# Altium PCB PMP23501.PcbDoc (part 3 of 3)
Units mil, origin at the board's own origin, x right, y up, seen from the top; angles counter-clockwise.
Board outline 4950 x 3450 mil, 4 copper layers (Top Layer, Layer 1, Layer 2, Bottom Layer), stack 70.356 mil thick; 186 components, 84 nets, 554 pads, 643 vias.
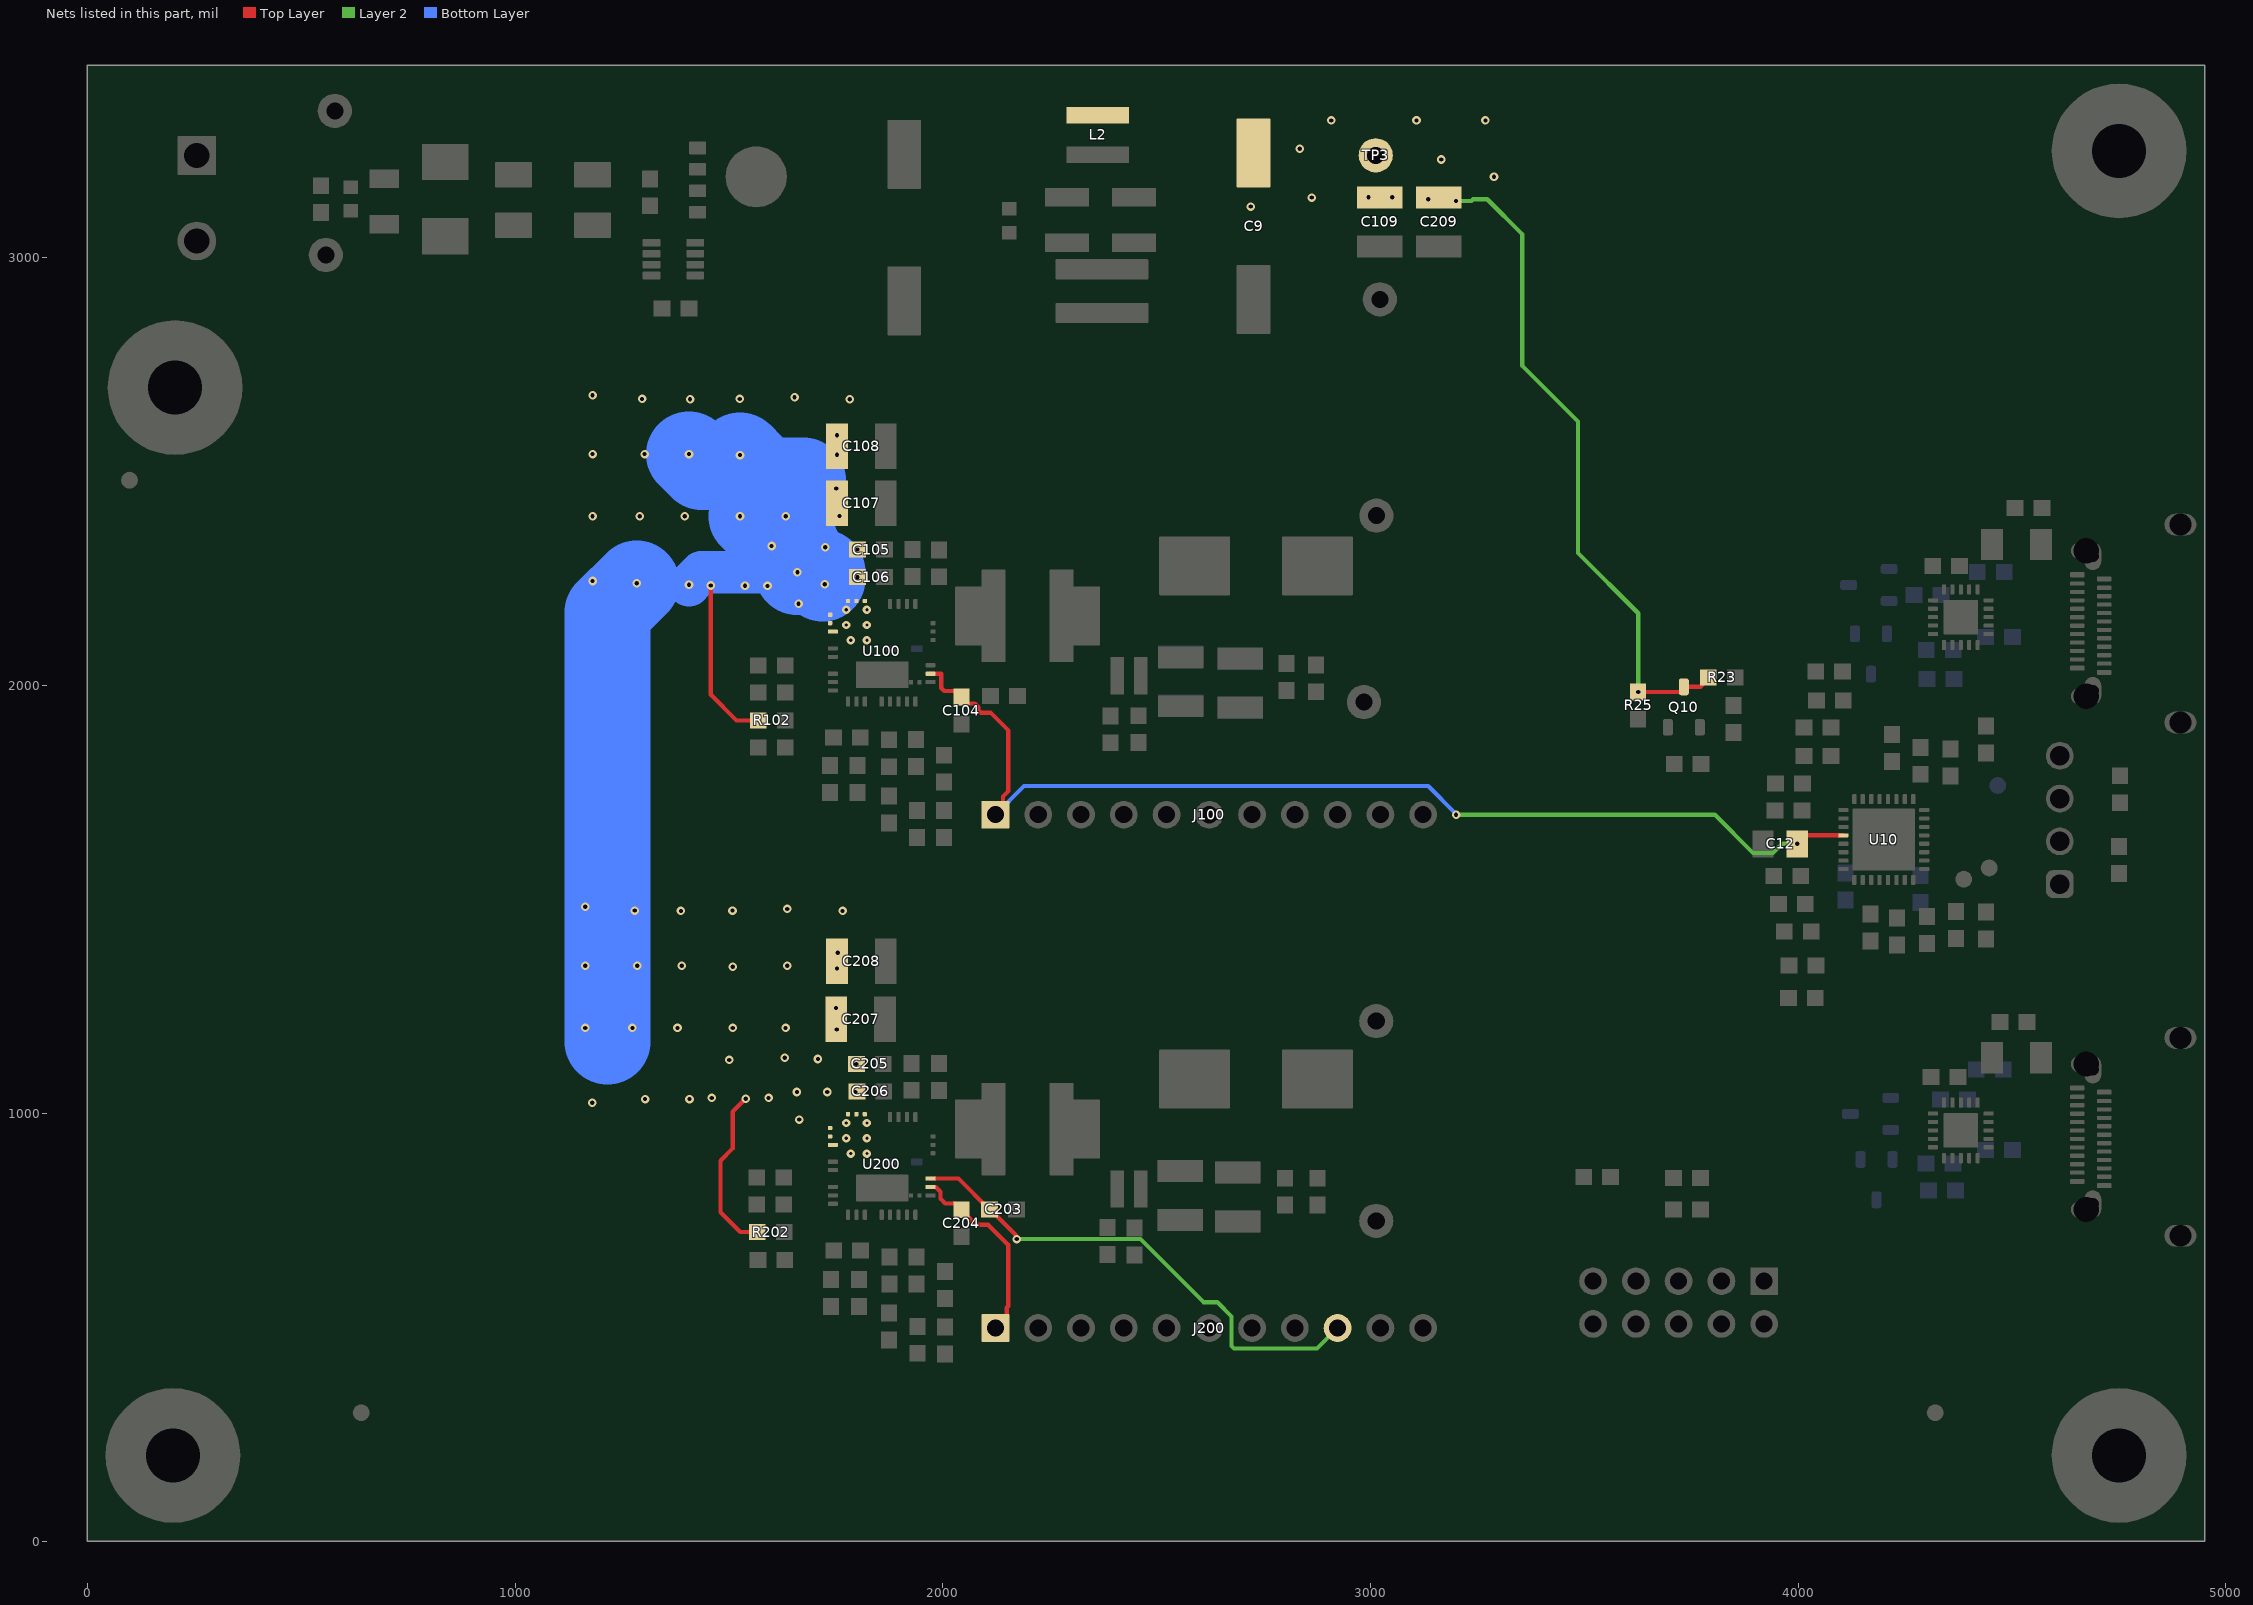
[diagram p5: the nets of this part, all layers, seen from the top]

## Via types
v1: diameter 20, hole 10, Top Layer to Bottom Layer, tented both sides, 592 vias
v2: diameter 19.68, hole 7.87, Top Layer to Bottom Layer, tented both sides, 46 vias
v3: diameter 16, hole 8, Top Layer to Bottom Layer, tented both sides, 4 vias
v4: diameter 20/20/20/20 (per signal layer), hole 10, Top Layer to Bottom Layer, tented bottom, 1 vias

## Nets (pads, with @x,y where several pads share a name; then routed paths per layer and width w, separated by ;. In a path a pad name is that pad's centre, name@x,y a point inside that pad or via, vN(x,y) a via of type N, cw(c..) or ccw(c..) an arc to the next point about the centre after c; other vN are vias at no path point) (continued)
VCC_B: C203.1 J200.9 U200.19 | length 1183.5
  Top Layer w10: U200.19@1971.17,847.47 2036.37,847.47 2108.29,775.56 C203.1@2109.27,775.56 2110.25,775.56 2171.09,714.73 2171.09,707.91 v1(2173,706) v1@2173,708.71
  Layer 2 w10: v1(2173,706) 2461.94,706 2609.44,558.5 2641.5,558.5 2675,525 2675,455.86 2680.86,450 2875,450 J200.9@2923,498
VDDA_A: C12.1 C104.2 J100.1 U10.4 U100.18 | length 2568.5
  Top Layer w10: U100.18@1970.75,2027.56 1996.23,2027.56 1996.23,1994.51 2003.27,1987.47 2029.8,1987.47 2043.5,1973.77 C104.2@2043.5,1972.95 C104.2@2051.04,1965.41 ; C104.2@2043.5,1958.11 2074.48,1958.11 2083.02,1949.57 2083.02,1942.62 2088.88,1936.76 2111.6,1936.76 2153.21,1895.15 2153.21,1753.35 2140.77,1740.9 2140.77,1715.96 J100.1@2122.99,1698.19 ; v1(3997.48,1630.16) 4017.17,1649.84 U10.4@4105.51,1649.84
  Layer 2 w10: v1(3200,1698) 3805,1698.19 3894.53,1608.66 3940.93,1608.66 3962.43,1630.16 v1(3997.48,1630.16)
  Bottom Layer w10: J100.1@2122.99,1698.19 2189.8,1765 3135,1765 3200,1700 v1(3200,1698)
VDDA_B: C204.2 J200.1 U200.18 | length 455.1
  Top Layer w10: U200.18@1971.17,827.79 1971.25,827.71 1983.41,827.71 1994.48,816.63 1994.48,800.52 2005.74,789.26 2029.8,789.26 2043.5,775.56 C204.2@2043.5,774.57 2043.5,773.59 2077.94,739.15 2106.29,739.15 2152.68,692.76 2152.68,548.86 2149.3,545.48 2149.3,524.3 J200.1@2123,498
Vin_48: C9.1 C105.1 C106.1 C107.1 C108.1 C109.1 C205.1 C206.1 C207.1 C208.1 C209.1 L2.2 Q10.3 R23.2 R25.1 R102.2 R202.2 TP3.1 U100.1 U100.2 U100.3 U100.27 U100.28 U100.29 U200.1 U200.2 U200.3 U200.27 U200.28 U200.29 | length 4583.7
  Top Layer w10: v1(1406.5,2235.51) v1@1408.31,2233.69 ; v1(1457.18,2234.06) 1457.18,1978.91 1517.44,1918.65 R102.2@1568.57,1918.65 ; v1(1538.99,1034) 1508.53,1003.54 1508.53,917.71 1479.98,889.17 1479.98,768.78 1526.36,722.4 R202.2@1566.25,722.4 R202.2@1561.36,727.3 ; v1(3625.85,1985.02) 3725.66,1985.02 3732.41,1991.77 Q10.3@3732.41,1996.98 3771.36,1996.98 3793.61,2019.24 R23.2@3797.55,2019.24
  Layer 2 w10: v1(3200,3133.17) 3235.82,3133.17 3239.77,3137.12 3272.88,3137.12 3355,3055 3355,2747.5 3485,2617.5 3485,2310 3625.85,2169.15 v1(3625.85,1985.02)
  Bottom Layer w100: v1(1406.5,2235.51) 1435.99,2265 v1(1660.05,2265)
  Bottom Layer w200: 1216.01,1167.65 1216.01,2171.39 v1(1284.13,2239.51) ; v1(1406.5,2541.24) 1436.86,2510.88 1521.43,2510.88 1551.79,2480.51 1674.17,2480.51 ; v1(1525.72,2539.01) 1551.79,2512.94 1551.79,2454.44 1601.29,2404.95 1601.29,2380.73 1660.05,2321.96 v1(1660.05,2265) ; 1660.05,2287.69 v1(1660.05,2265) ; 1660.05,2326.32 v1(1660.05,2265) ; 1719.31,2249.42 1719.31,2265 v1(1660.05,2265) ; 1551.79,2395.94 1579.6,2368.13 1551.79,2395.94
  other v1: 1664.11,985.27 1180,1025 1303.82,1033.2 1407.69,1033.2 1460,1035.94 1592.66,1035.94 1658.95,1049.82 1729.84,1049.82 1795.08,1049.82 1797.86,1115.52 1500.72,1124.71 1708,1126.99 1630.13,1130 1751.68,1195.94 1164.11,1199.71 1274.28,1199.71 1379.66,1199.71 1508.72,1199.71 1632.35,1199.71 1750.02,1246.36 1752.44,1338.5 1508.72,1342.77 1164.11,1345 1285.67,1345 1389.5,1345 1636.3,1345 1754.13,1375.5 1387.72,1473.08 1765.61,1473.08 1279.81,1473.96 1508.27,1473.96 1636.3,1477.8 1164.11,1482.66 1662.65,2191.17 1590,2233.02 1537.39,2233.69 1724.14,2236.97 1181.1,2244.6 1800.6,2253.32 1800.6,2318.1 1725,2323.23 1599.65,2326.32 1181.1,2395.94 1291.27,2395.94 1396.66,2395.94 1525.72,2395.94 1632.55,2395.94 1758.36,2396.32 1750.66,2461 1752.44,2539.69 1181.1,2541.24 1302.66,2541.24 1752.44,2585 1409,2669.32 1782.6,2669.32 1296.8,2670.2 1525.26,2670.2 1653.3,2674.04 1181.1,2678.9 2720,3120 3135,3137.12 2862.64,3141.07 2995,3141.73 3050.56,3141.73 3288.65,3190 3165,3230 2834.2,3255 2908.04,3321.35 3107.46,3321.35 3268.54,3321.35
  other v2: 1784.8,905.9 1822.55,905.9 1774.32,941.65 1822.55,941.65 1774.32,977.39 1822.55,977.39 1784.8,2105.9 1822.55,2105.9 1774.32,2141.65 1822.55,2141.65 1774.32,2177.39 1822.55,2177.39
pads on no net: FID1.1 FID2.1 FID3.1 H1.0 H2.1 H3.0 H4.1 H5.0 H6.1 H7.0 H8.1 J30.1 J30.2 J30.3 J30.4 J30.7 J30.8 J130.A2 J130.A3 J130.A8 J130.A10 J130.A11 J130.B2 J130.B3 J130.B8 J130.B10 J130.B11 J230.A2 J230.A3 J230.A8 J230.A10 J230.A11 J230.B2 J230.B3 J230.B8 J230.B10 J230.B11 LBL1.0 U1.3 U1.7 U1.8 U100.10 U140.9 U140.16 U140.17 U140.19 U140.20 U200.10 U240.9 U240.16 U240.17 U240.19 U240.20

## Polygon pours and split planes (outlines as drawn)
GND on Top Layer "TOP_LAYER_GND_P000" (solid, remove dead copper, pour order 0): 4105.5,2281.22 4105.5,2092.45 4133.7,2092.45 4522.18,2092.45 4522.18,2193.48 4409.77,2302.12 4391.21,2302.12 4126.4,2302.12
GND on Top Layer "TOP_LAYER_GND_P035" (solid, remove dead copper, pour order 35): 33.55,2863.05 1212.99,2863.05 1212.99,3442.34 4933.55,3442.34 4933.55,47.34 33.55,47.34
GND on Top Layer "TOP_LAYER_GND_P034" (solid, remove dead copper, pour order 34): 1872.2,2181.88 1937.29,2181.88 1937.29,2196.36 1929.4,2265 1891.31,2265 1891.31,2217.38 1872.2,2198.28
AGND_B on Top Layer "TOP_LAYER_AGND_B_P032" (solid, remove dead copper, pour order 32): 1959.77,816.63 1959.77,661.25 1787.04,661.25 1787.04,667.7 1784.8,669.94 1539,669.94 1539,587.71 1744.63,382.08 2156.36,382.08 2156.36,742.74 2063.4,742.74 1989.5,816.63
AGND_A on Top Layer "TOP_LAYER_AGND_A_P030" (solid, remove dead copper, pour order 30): 1960.51,2013.07 1959.21,2011.77 1959.21,1866.64 1786.48,1866.64 1786.48,1873.08 1784.24,1875.33 1550.04,1875.33 1550.04,1781.5 1741.54,1590 2155.8,1590 2155.8,1948.12 2062.84,1948.12 1997.89,2013.07
VBUS_B on Top Layer "TOP_LAYER_VBUS_B_P028" (solid, remove dead copper, pour order 28): 2710,1335 3457.28,1335 3457.28,1056.63 3457.28,818.19 2710,818.19
VBUS_B on Top Layer "TOP_LAYER_VBUS_B_P025" (solid, remove dead copper, pour order 25): 2440,760 2474.87,760 2485.7,770.83 2485.7,811.54 2754.19,811.54 2764.58,821.93 2984.2,821.93 2984.2,1134.11 3068.59,1218.5 3068.59,1224.69 3050.56,1224.69 3013.35,1261.91 2947.39,1195.94 2756.5,1195.94 2756.5,964.46 2440,964.46 2440,896.14
NetL200_2 on Top Layer "TOP_LAYER_NETL200_2_P024" (solid, remove dead copper, pour order 24): 2250,1065 2342.21,1065 2372.57,1034.64 2372.57,929.13 2375.07,929.13 2427.47,876.73 2427.47,799.28 2398.61,799.28 2250,799.28
VBUS_A on Top Layer "TOP_LAYER_VBUS_A_P023" (solid, remove dead copper, pour order 23): 2710,2465.59 4671.95,2465.59 4671.95,2018.19 2710,2018.19
GND on Top Layer "TOP_LAYER_GND_P022" (solid, remove dead copper, pour order 22): 1832.68,2805 1848.9,2821.22 1848.9,3094.57 3230,3094.57 3230,2950.97 3074.15,2795.13 2762.97,2795.13 2655,2903.09 2196.24,2903.09 2130,2836.85 2130,2800 1839.15,2800 1834.15,2805
Vin_48 on Top Layer "TOP_LAYER_VIN_48_P021" (solid, remove dead copper, pour order 21): 2290,3360 2290.07,3359.93 2290.07,3281.48 2568.52,3281.48 2598.55,3251.45 2598.55,3089.57 3307.79,3089.57 3328.74,3110.52 3328.74,3360
V_Batt_Protected on Top Layer "TOP_LAYER_V_BATT_PROTECTED_P020" (solid, remove dead copper, pour order 20): 1484.3,3336.61 2035.53,3336.61 2117.14,3255 2520,3255 2520,3094.57 2525,3089.57 1486.94,3089.57 1484.3,3092.21 1484.3,3334.06
NetC3_1 on Top Layer "TOP_LAYER_NETC3_1_P017" (solid, remove dead copper, pour order 17): 1216.01,3224.24 1292.02,3224.24 1330.01,3262.23 1450,3262.23 1450,3142.23 1455,3137.23 1450.08,3132.31 1387.69,3132.31 1370,3150 1369.42,3149.42 1216.01,3149.42
EMIGND on Top Layer "TOP_LAYER_EMIGND_P016" (solid, remove dead copper, pour order 16): 202.33,3134.43 200.88,3132.98 200.88,2984.41 958.5,2984.41 958.5,3141.37 192.15,3141.37
NetC0_1 on Top Layer "TOP_LAYER_NETC0_1_P013" (solid, remove dead copper, pour order 13): 202.33,3402.33 202.33,3134.43 961.07,3134.43 961.07,3290 739.41,3290 653.98,3375.43 653.98,3405.68 205.68,3405.68
VBUS_A on Top Layer "TOP_LAYER_VBUS_A_P012" (solid, remove dead copper, pour order 12): 2440,1960 2474.87,1960 2485.7,1970.83 2485.7,2011.54 2754.19,2011.54 2764.58,2021.93 2984.2,2021.93 2984.2,2334.11 3068.59,2418.5 3068.59,2424.69 3050.56,2424.69 3013.35,2461.91 2947.39,2395.94 2756.5,2395.94 2756.5,2164.46 2440,2164.46 2440,2096.14
NetL100_2 on Top Layer "TOP_LAYER_NETL100_2_P010" (solid, remove dead copper, pour order 10): 2250,2265 2342.21,2265 2372.57,2234.64 2372.57,2129.13 2375.07,2129.13 2427.47,2076.73 2427.47,1999.28 2398.61,1999.28 2250,1999.28
Vin_48 on Top Layer "TOP_LAYER_VIN_48_P009" (solid, remove dead copper, pour order 9): 1125,2712.8 1839.09,2712.8 1839.09,2114.28 1778.43,2114.28 1777.1,2112.95 1770.72,2119.32 1724.14,2119.32 1694.73,2166.38 1694.73,2169.45 1125,2169.45
Vin_48 on Top Layer "TOP_LAYER_VIN_48_P008" (solid, remove dead copper, pour order 8): 1125,1513 1839.09,1513 1839.09,914.47 1778.43,914.47 1777.1,913.14 1770.72,919.52 1724.14,919.52 1694.73,966.57 1694.73,969.64 1125,969.64
NetC212_1 on Top Layer "TOP_LAYER_NETC212_1_P007" (solid, remove dead copper, pour order 7): 2151.27,1075.4 2151.27,857.74 2147.72,854.18 2085.78,854.18 2085.78,860.83 2071.14,875.47 1851.16,876.8 1851.16,961.7 1852.05,962.59 1959.21,962.59 1959.21,1075.4
NetC112_1 on Top Layer "TOP_LAYER_NETC112_1_P004" (solid, remove dead copper, pour order 4): 2155.51,2277.93 2155.51,2055.92 2153.77,2054.18 2085.78,2054.18 2085.78,2060.83 2064.93,2081.69 1835.15,2081.69 1835.15,2168.54 1935.4,2168.54 1935.4,2277.93 2087.91,2277.93
VBUS_B on Top Layer "TOP_LAYER_VBUS_B_P003" (solid, remove dead copper, pour order 3): 3411.1,1176.31 4400.12,1176.3 4400.12,1205.8 4456.84,1262.51 4500.4,1262.51 4500.4,1129.6 4618.07,1011.93 4691.96,1011.93 4691.96,833.29 4670.23,811.57 3931.18,811.57 3814.16,928.59 3411.1,928.59
GND on Top Layer "TOP_LAYER_GND_P002" (solid, remove dead copper, pour order 2): 4111.98,1087.08 4111.98,870.29 4113.36,871.68 4520.19,871.68 4520.19,991.05 4407.78,1099.69 4389.22,1099.69 4124.4,1099.69 4109.71,1085
GND on Layer 1 "LAYER_1_GND_P005" (solid, remove dead copper, pour order 5): 6,3442 10,3438 10,16 4936,16 4940,12 4940,3438 6,3438 2,3434
Vin_48 on Bottom Layer "BOTTOM_LAYER_VIN_48_P027" (solid, remove dead copper, pour order 27): 2845,3315 2889.93,3359.93 3325,3359.93 3325,3069.89 3314.32,3059.21 3062.23,3059.21 2184.9,2181.88 2176.7,2190.08 1751.67,2190.08 1751.67,2593.27 1813.41,2655 2186.24,2655 2851.94,3320.7
GND on Bottom Layer "BOTTOM_LAYER_GND_P033" (solid, remove dead copper, pour order 33): 24.43,2834.35 1210.59,2834.35 1210.59,3421.55 4924.43,3421.55 4924.43,26.55 24.43,26.55
Vin_48 on Bottom Layer "BOTTOM_LAYER_VIN_48_P015" (solid, remove dead copper, pour order 15): 1122.46,1513 1122.46,969.64 1659.7,969.64 1757.81,871.54 1839.09,871.54 1839.09,1513
Vin_48 on Bottom Layer "BOTTOM_LAYER_VIN_48_P014" (solid, remove dead copper, pour order 14): 1125,2712.8 1125,2141.42 1695.47,2141.42 1741.48,2095.41 1858.04,2095.41 1858.04,2712.8
GND on Layer 2 "LAYER_2_GND_P029" (solid, remove dead copper, pour order 29): 21.51,2840 1210,2840 1210,3420.06 4921.51,3420.06 4921.51,25.06 21.51,25.06

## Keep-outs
Keep-Out Layer:
  lines w5: -2.5,0 ccw(c0,0) 0,-2.5 ; -2.5,0 ccw(c0,0) 0,-2.5 ; -2.5,0 -2.5,3450 ; -2.5,3450 cw(c0,3450) 0,3452.5 ; -2.5,3450 cw(c0,3450) 0,3452.5 ; 0,-2.5 4950,-2.5 ; 0,3452.5 4950,3452.5 ; 4741.4,755.06 ccw(c4743.9,755.06) 4741.59,754.1 ; 4741.4,755.06 ccw(c4743.9,755.06) 4741.58,754.11 ; 4741.4,755.06 4741.4,758.95 ; 4741.4,758.95 cw(c4743.9,758.98) 4741.4,758.98 ; 4741.4,758.95 cw(c4743.9,758.98) 4741.4,758.98 ; 4741.4,758.95 4741.4,758.98 ; 4741.4,758.98 4741.4,1131.02 4741.4,1134.94 ; 4741.4,1134.94 cw(c4743.9,1134.94) 4741.58,1135.89 ; 4741.4,1134.94 cw(c4743.9,1134.94) 4741.59,1135.9 ; 4741.4,1955.06 ccw(c4743.9,1955.06) 4741.59,1954.1 ; 4741.4,1955.06 ccw(c4743.9,1955.06) 4741.58,1954.11 ; 4741.4,1955.06 4741.4,1958.95 ; 4741.4,1958.95 cw(c4743.9,1958.98) 4741.4,1958.98 ; 4741.4,1958.95 cw(c4743.9,1958.98) 4741.4,1958.98 ; 4741.4,1958.95 4741.4,1958.98 ; 4741.4,1958.98 4741.4,2331.02 4741.4,2334.94 ; 4741.4,2334.94 cw(c4743.9,2334.94) 4741.58,2335.89 ; 4741.4,2334.94 cw(c4743.9,2334.94) 4741.59,2335.9 ; 4741.58,754.11 ccw(c4743.9,755.06) 4741.59,754.1 ; 4741.58,754.11 4741.59,754.1 ; 4741.59,754.1 4741.59,754.1 ; 4741.59,754.1 4744.58,746.88 ; 4741.59,1135.9 ccw(c4743.9,1134.94) 4741.58,1135.89 ; 4741.59,1135.9 4744.58,1143.12 ; 4741.59,1135.9 4741.59,1135.9 ; 4741.58,1135.89 4741.59,1135.9 ; 4741.58,1954.11 ccw(c4743.9,1955.06) 4741.59,1954.1 ; 4741.58,1954.11 4741.59,1954.1 ; 4741.59,1954.1 4741.59,1954.1 ; 4741.59,1954.1 4744.58,1946.88 ; 4741.59,2335.9 ccw(c4743.9,2334.94) 4741.58,2335.89 ; 4741.59,2335.9 4744.58,2343.12 ; 4741.59,2335.9 4741.59,2335.9 ; 4741.58,2335.89 4741.59,2335.9 ; 4744.58,746.87 ccw(c4746.89,747.83) 4745.13,746.06 ; 4744.59,746.86 ccw(c4746.89,747.83) 4745.13,746.06 ; 4744.59,746.86 cw(c4746.89,747.83) 4744.58,746.88 ; 4744.58,746.87 4744.58,746.88 ; 4744.58,746.87 4744.59,746.86 ; 4744.58,1143.12 cw(c4746.89,1142.17) 4744.59,1143.14 ; 4744.58,1143.12 4744.58,1143.13 ; 4744.58,1143.13 cw(c4746.89,1142.17) 4745.13,1143.94 ; 4744.59,1143.14 cw(c4746.89,1142.17) 4745.13,1143.94 ; 4744.58,1143.13 4744.59,1143.14 ; 4744.58,1946.87 ccw(c4746.89,1947.83) 4745.13,1946.06 ; 4744.59,1946.86 ccw(c4746.89,1947.83) 4745.13,1946.06 ; 4744.59,1946.86 cw(c4746.89,1947.83) 4744.58,1946.88 ; 4744.58,1946.87 4744.58,1946.88 ; 4744.58,1946.87 4744.59,1946.86 ; 4744.58,2343.12 cw(c4746.89,2342.17) 4744.59,2343.14 ; 4744.58,2343.12 4744.58,2343.13 ; 4744.58,2343.13 cw(c4746.89,2342.17) 4745.13,2343.94 ; 4744.59,2343.14 cw(c4746.89,2342.17) 4745.13,2343.94 ; 4744.58,2343.13 4744.59,2343.14 ; 4745.13,746.06 4750.66,740.52 ; 4745.13,1143.94 4750.66,1149.48 ; 4745.13,1946.06 4750.66,1940.52 ; 4745.13,2343.94 4750.66,2349.48 ; 4746.4,758.98 ccw(c4743.9,758.98) 4746.4,759 ; 4746.4,758.98 ccw(c4743.9,758.98) 4746.4,759 ; 4746.4,759 4746.4,1131.02 4746.4,1134.44 4749.01,1140.76 4753.85,1145.59 4760.16,1148.21 4767,1148.21 4773.32,1145.59 4778.15,1140.76 4780.77,1134.44 4780.77,1131.02 ; 4746.4,758.98 4746.4,759 ; 4746.4,758.98 4746.4,755.56 4749.01,749.24 4753.85,744.41 4760.16,741.79 4767,741.79 4773.32,744.41 4778.15,749.24 4780.77,755.56 4780.77,758.98 ; 4746.4,1958.98 ccw(c4743.9,1958.98) 4746.4,1959 ; 4746.4,1958.98 ccw(c4743.9,1958.98) 4746.4,1959 ; 4746.4,1959 4746.4,2331.02 4746.4,2334.44 4749.01,2340.76 4753.85,2345.59 4760.16,2348.21 4767,2348.21 4773.32,2345.59 4778.15,2340.76 4780.77,2334.44 4780.77,2331.02 ; 4746.4,1958.98 4746.4,1959 ; 4746.4,1958.98 4746.4,1955.56 4749.01,1949.24 4753.85,1944.41 4760.16,1941.79 4767,1941.79 4773.32,1944.41 4778.15,1949.24 4780.77,1955.56 4780.77,1958.98 ; 4750.66,740.52 ccw(c4752.43,742.29) 4751.47,739.98 ; 4750.66,740.52 ccw(c4752.43,742.29) 4751.47,739.98 ; 4750.66,1149.48 cw(c4752.43,1147.71) 4751.47,1150.02 ; 4750.66,1149.48 cw(c4752.43,1147.71) 4751.47,1150.02 ; 4750.66,1940.52 ccw(c4752.43,1942.29) 4751.47,1939.98 ; 4750.66,1940.52 ccw(c4752.43,1942.29) 4751.47,1939.98 ; 4750.66,2349.48 cw(c4752.43,2347.71) 4751.47,2350.02 ; 4750.66,2349.48 cw(c4752.43,2347.71) 4751.47,2350.02 ; 4751.47,739.98 ccw(c4752.43,742.29) 4751.48,739.97 ; 4751.47,739.98 4751.48,739.97 ; 4751.47,739.98 4751.47,739.98 ; 4751.47,1150.02 cw(c4752.43,1147.71) 4751.48,1150.03 ; 4751.47,1150.02 4751.48,1150.03 ; 4751.47,1150.02 4751.47,1150.02 ; 4751.47,1939.98 ccw(c4752.43,1942.29) 4751.48,1939.97 ; 4751.47,1939.98 4751.48,1939.97 ; 4751.47,1939.98 4751.47,1939.98 ; 4751.47,2350.02 cw(c4752.43,2347.71) 4751.48,2350.03 ; 4751.47,2350.02 4751.48,2350.03 ; 4751.47,2350.02 4751.47,2350.02 ; 4751.48,739.97 4758.7,736.98 ; 4751.48,1150.03 4758.7,1153.02 ; 4751.48,1939.97 4758.7,1936.98 ; 4751.48,2350.03 4758.7,2353.02 ; 4758.72,736.98 ccw(c4759.67,739.29) 4759.67,736.79 ; 4758.7,736.98 ccw(c4759.67,739.29) 4758.72,736.98 ; 4758.71,736.98 ccw(c4759.67,739.29) 4759.67,736.79 ; 4758.71,736.98 4758.72,736.98 ; 4758.7,736.98 4758.71,736.98 ; 4758.71,1153.02 cw(c4759.67,1150.71) 4759.67,1153.21 ; 4758.72,1153.02 ccw(c4759.67,1150.71) 4758.7,1153.02 ; 4758.72,1153.02 cw(c4759.67,1150.71) 4759.67,1153.21 ; 4758.71,1153.02 4758.72,1153.02 ; 4758.7,1153.02 4758.71,1153.02 ; 4758.71,1936.98 ccw(c4759.67,1939.29) 4759.67,1936.79 ; 4758.72,1936.98 ccw(c4759.67,1939.29) 4759.67,1936.79 ; 4758.7,1936.98 ccw(c4759.67,1939.29) 4758.72,1936.98 ; 4758.71,1936.98 4758.72,1936.98 ; 4758.7,1936.98 4758.71,1936.98 ; 4758.71,2353.02 cw(c4759.67,2350.71) 4759.67,2353.21 ; 4758.72,2353.02 ccw(c4759.67,2350.71) 4758.7,2353.02 ; 4758.72,2353.02 cw(c4759.67,2350.71) 4759.67,2353.21 ; 4758.71,2353.02 4758.72,2353.02 ; 4758.7,2353.02 4758.71,2353.02 ; 4759.67,736.79 4767.5,736.79 ; 4759.67,1153.21 4767.5,1153.21 ; 4759.67,1936.79 4767.5,1936.79 ; 4759.67,2353.21 4767.5,2353.21 ; 4767.5,736.79 ccw(c4767.5,739.29) 4768.45,736.98 ; 4767.5,736.79 ccw(c4767.5,739.29) 4768.46,736.98 ; 4767.5,1153.21 cw(c4767.5,1150.71) 4768.45,1153.02 ; 4767.5,1153.21 cw(c4767.5,1150.71) 4768.46,1153.02 ; 4767.5,1936.79 ccw(c4767.5,1939.29) 4768.45,1936.98 ; 4767.5,1936.79 ccw(c4767.5,1939.29) 4768.46,1936.98 ; 4767.5,2353.21 cw(c4767.5,2350.71) 4768.45,2353.02 ; 4767.5,2353.21 cw(c4767.5,2350.71) 4768.46,2353.02 ; 4768.45,736.98 ccw(c4767.5,739.29) 4768.46,736.98 ; 4768.46,736.98 4775.68,739.97 ; 4768.46,736.98 4768.46,736.98 ; 4768.45,736.98 4768.46,736.98 ; 4768.46,1153.02 ccw(c4767.5,1150.71) 4768.45,1153.02 ; 4768.46,1153.02 4775.68,1150.03 ; 4768.46,1153.02 4768.46,1153.02 ; 4768.45,1153.02 4768.46,1153.02 ; 4768.45,1936.98 ccw(c4767.5,1939.29) 4768.46,1936.98 ; 4768.46,1936.98 4775.68,1939.97 ; 4768.46,1936.98 4768.46,1936.98 ; 4768.45,1936.98 4768.46,1936.98 ; 4768.46,2353.02 ccw(c4767.5,2350.71) 4768.45,2353.02 ; 4768.46,2353.02 4775.68,2350.03 ; 4768.46,2353.02 4768.46,2353.02 ; 4768.45,2353.02 4768.46,2353.02 ; 4775.68,739.97 ccw(c4774.73,742.29) 4775.7,739.98 ; 4775.68,739.97 4775.69,739.98 ; 4775.69,739.98 ccw(c4774.73,742.29) 4776.5,740.52 ; 4775.7,739.98 ccw(c4774.73,742.29) 4776.5,740.52 ; 4775.69,739.98 4775.7,739.98 ; 4775.69,1150.02 cw(c4774.73,1147.71) 4776.5,1149.48 ; 4775.7,1150.02 ccw(c4774.73,1147.71) 4775.68,1150.03 ; 4775.7,1150.02 cw(c4774.73,1147.71) 4776.5,1149.48 ; 4775.69,1150.02 4775.7,1150.02 ; 4775.69,1150.02 4775.68,1150.03 ; 4775.68,1939.97 ccw(c4774.73,1942.29) 4775.7,1939.98 ; 4775.68,1939.97 4775.69,1939.98 ; 4775.69,1939.98 ccw(c4774.73,1942.29) 4776.5,1940.52 ; 4775.7,1939.98 ccw(c4774.73,1942.29) 4776.5,1940.52 ; 4775.69,1939.98 4775.7,1939.98 ; 4775.69,2350.02 cw(c4774.73,2347.71) 4776.5,2349.48 ; 4775.7,2350.02 ccw(c4774.73,2347.71) 4775.68,2350.03 ; 4775.7,2350.02 cw(c4774.73,2347.71) 4776.5,2349.48 ; 4775.69,2350.02 4775.7,2350.02 ; 4775.69,2350.02 4775.68,2350.03 ; 4776.5,740.52 4782.04,746.06 ; 4776.5,1149.48 4782.04,1143.94 ; 4776.5,1940.52 4782.04,1946.06 ; 4776.5,2349.48 4782.04,2343.94 ; 4780.77,758.98 cw(c4783.27,758.98) 4783.27,761.48 ; 4780.77,758.98 cw(c4783.27,758.98) 4783.27,761.48 ; 4780.77,1131.02 ccw(c4783.27,1131.02) 4783.27,1128.52 ; 4780.77,1131.02 ccw(c4783.27,1131.02) 4783.27,1128.52 ; 4780.77,1958.98 cw(c4783.27,1958.98) 4783.27,1961.48 ; 4780.77,1958.98 cw(c4783.27,1958.98) 4783.27,1961.48 ; 4780.77,2331.02 ccw(c4783.27,2331.02) 4783.27,2328.52 ; 4780.77,2331.02 ccw(c4783.27,2331.02) 4783.27,2328.52 ; 4782.04,746.06 ccw(c4780.27,747.83) 4782.58,746.86 ; 4782.04,746.06 ccw(c4780.27,747.83) 4782.58,746.87 ; 4782.04,1143.94 cw(c4780.27,1142.17) 4782.58,1143.13 ; 4782.04,1143.94 cw(c4780.27,1142.17) 4782.58,1143.14 ; 4782.04,1946.06 ccw(c4780.27,1947.83) 4782.58,1946.86 ; 4782.04,1946.06 ccw(c4780.27,1947.83) 4782.58,1946.87 ; 4782.04,2343.94 cw(c4780.27,2342.17) 4782.58,2343.14 ; 4782.04,2343.94 cw(c4780.27,2342.17) 4782.58,2343.13 ; 4782.58,746.86 ccw(c4780.27,747.83) 4782.58,746.88 ; 4782.58,746.87 4782.59,746.88 ; 4782.58,746.86 4782.58,746.87 ; 4782.59,746.88 4785.57,754.09 ; 4782.58,1143.12 ccw(c4780.27,1142.17) 4782.58,1143.14 ; 4782.59,1143.12 4782.58,1143.13 ; 4782.59,1143.12 4785.57,1135.9 ; 4782.58,1143.14 4782.58,1143.13 ; 4782.58,1946.86 ccw(c4780.27,1947.83) 4782.58,1946.88 ; 4782.58,1946.87 4782.59,1946.88 ; 4782.58,1946.86 4782.58,1946.87 ; 4782.59,1946.88 4785.57,1954.09 ; 4782.58,2343.12 ccw(c4780.27,2342.17) 4782.58,2343.14 ; 4782.59,2343.12 4782.58,2343.13 ; 4782.59,2343.12 4785.57,2335.9 ; 4782.58,2343.14 4782.58,2343.13 ; 4783.27,761.48 4950,761.48 ; 4783.27,1128.52 4950,1128.52 ; 4783.27,1961.48 4950,1961.48 ; 4783.27,2328.52 4950,2328.52 ; 4785.57,754.1 ccw(c4783.27,755.06) 4785.58,754.11 ; 4785.57,754.09 4785.58,754.1 ; 4785.57,1135.9 cw(c4783.27,1134.94) 4785.58,1135.89 ; 4785.57,1135.9 4785.58,1135.9 ; 4785.57,1954.1 ccw(c4783.27,1955.06) 4785.58,1954.11 ; 4785.57,1954.09 4785.58,1954.1 ; 4785.57,2335.9 cw(c4783.27,2334.94) 4785.58,2335.89 ; 4785.57,2335.9 4785.58,2335.9 ; 4785.58,754.11 ccw(c4783.27,755.06) 4785.77,755.06 ; 4785.58,754.1 ccw(c4783.27,755.06) 4785.77,755.06 ; 4785.58,754.1 4785.58,754.11 ; 4785.58,1135.9 cw(c4783.27,1134.94) 4785.77,1134.94 ; 4785.58,1135.89 cw(c4783.27,1134.94) 4785.77,1134.94 ; 4785.58,1135.9 4785.58,1135.89 ; 4785.58,1954.1 ccw(c4783.27,1955.06) 4785.77,1955.06 ; 4785.58,1954.11 ccw(c4783.27,1955.06) 4785.77,1955.06 ; 4785.58,1954.1 4785.58,1954.11 ; 4785.58,2335.89 cw(c4783.27,2334.94) 4785.77,2334.94 ; 4785.58,2335.9 cw(c4783.27,2334.94) 4785.77,2334.94 ; 4785.58,2335.9 4785.58,2335.89 ; 4785.77,755.06 4785.77,756.48 4947.5,756.48 4947.5,2.5 2.5,2.5 2.5,3447.5 4947.5,3447.5 4947.5,2333.52 4785.77,2333.52 4785.77,2334.94 ; 4785.77,1134.94 4785.77,1133.52 4947.5,1133.52 4947.5,1956.48 4785.77,1956.48 4785.77,1955.06 ; 4950,-2.5 ccw(c4950,0) 4952.5,0 ; 4950,-2.5 ccw(c4950,0) 4952.5,0 ; 4950,761.48 cw(c4950,758.98) 4952.5,758.98 ; 4950,761.48 cw(c4950,758.98) 4952.5,758.98 ; 4950,1128.52 ccw(c4950,1131.02) 4952.5,1131.02 ; 4950,1128.52 ccw(c4950,1131.02) 4952.5,1131.02 ; 4950,1961.48 cw(c4950,1958.98) 4952.5,1958.98 ; 4950,1961.48 cw(c4950,1958.98) 4952.5,1958.98 ; 4950,2328.52 ccw(c4950,2331.02) 4952.5,2331.02 ; 4950,2328.52 ccw(c4950,2331.02) 4952.5,2331.02 ; 4950,3452.5 cw(c4950,3450) 4952.5,3450 ; 4950,3452.5 cw(c4950,3450) 4952.5,3450 ; 4952.5,0 4952.5,758.98 ; 4952.5,1131.02 4952.5,1958.98 ; 4952.5,2331.02 4952.5,3450
  text ".Layer_Name" at 577,-858.49 h60

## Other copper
Top Layer:
  text ".Layer_Name" at 577,-858.49 h60
Layer 1:
  pour cut-out: 10,3437.79 10,2840 1210,2840 1210,3434.79 13,3434.79
Bottom Layer:
  text ".Layer_Name" at 577,-858.49 h60

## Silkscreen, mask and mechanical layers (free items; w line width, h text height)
Top Overlay:
  text "Vin +" at 33.62,3390.55 h75
  text "Vin to DCDCs" at 3074.15,3257.22 h50
  text "GND" at 3088.73,2893.79 h50
  text "Vin -" at 63.28,2870 h75
  text "24Vin / 48Vin for SPR" at 446.29,2740.67 h60
  text "48Vin for EPR" at 463.98,2611.55 h30
  text "20Vout / 5A max for SPR" at 4295.91,2605.67 h60
  text "48Vout / 5A max for EPR" at 4301.22,2545.67 h60
  text "10A max" at 545.77,2486.32 h30
  text "CAUTION:" at 2018.3,2393.21 h60
  text "Hot Surface" at 2275.69,2393.21 h60
  text "VBUS_A" at 3000.05,2290.4 h50
  text "GND" at 3047.49,1976.44 h50
  text "debug" at 4480.52,1862.17 h30
  text "I2C to Host data" at 4364.4,1726.61 h30
  text "I2C to H. clock" at 4387.79,1648.47 h30
  text "DCDC_A" at 2715,1638.8 h30 r270
  text "PA_SYNC" at 2206.19,1636.12 h30 r270
  text "EN/UVLO_A" at 2415.79,1636.12 h30 r270
  text "COMP_A" at 2616.72,1634.16 h30 r270
  text "nINT-DCDCs" at 2792.13,1634.16 h30 r270
  text "IMON_A" at 3015.91,1631.65 h30 r270
  text "VCC_A" at 2915.22,1630.93 h30 r270
  text "VDDA_A" at 2083.26,1629.97 h30 r270
  text "GND" at 2307.34,1629.97 h30 r270
  text "GND" at 2521.91,1629.97 h30 r270
  text "GND" at 3121.91,1627.82 h30 r270
  text "'.PRJ_Number'.PCB_Rev" at 161.98,1605 h108.27
  text "GND" at 4688.54,1509.98 h30 r90
  text "DCDC_B" at 2895.05,1293.18 h50
  text "Hot Surface" at 2275,1216.18 h60
  text "CAUTION:" at 2014.99,1214.4 h60
  text "GND" at 3046.93,669.03 h50
  text "20Vout / 5A max for SPR" at 4291.05,640.71 h60
  text "48Vout / 5A max for EPR" at 4293.12,562.2 h60
  text "EN/UVLO_B" at 2410.67,433.31 h30 r270
  text "COMP_B" at 2630.32,433.31 h30 r270
  text "GND" at 2281.3,431.55 h30 r270
  text "GND" at 2513.92,431.55 h30 r270
  text "PB_SYNC" at 2206.19,431.12 h30 r270
  text "DCDC_B" at 2715.23,430.8 h30 r270
  text "VCC_B" at 2895.05,430.77 h30 r270
  text "IMON_B" at 3015.92,430.8 h30 r270
  text "VDDA_B" at 2083.44,427.77 h30 r270
  text "nINT-DCDCs" at 2810.24,422.3 h30 r270
  text "GND" at 3121.92,417.96 h30 r270
  text "I2C for DCDCs" at 3503.98,313.55 h60
  text ".Layer_Name" at 577,-858.49 h60
Bottom Overlay:
  text ".Layer_Name" at 577,-858.49 h60
Top Paste:
  text ".Layer_Name" at 577,-858.49 h60
Bottom Paste:
  text ".Layer_Name" at 577,-858.49 h60
Top Solder:
  text ".Layer_Name" at 577,-858.49 h60
  text ".Layer_Name" at 577,-858.49 h60
Bottom Solder:
  text ".Layer_Name" at 577,-858.49 h60
Drill Guide:
  text ".Layer_Name" at 577,-858.49 h60
M1 Board Outline:
  the board outline again, w10
  text ".Layer_Name" at 577,-858.49 h60
M2 Board Dimensions:
  rectangle: 0,-275 125,-150
  rectangle: 125,-400 500,-275
  lines w7: 0,-275 1000,-275 ; 125,-400 125,-150 ; 250,-400 250,-150 ; 500,-400 500,-150 ; 750,-400 750,-150 ; 0,-400 1000,-400 1000,-150 0,-150 0,-400
  text ".Layer_Name" at 577,-858.49 h60
M3 3D STEP Top:
  text ".Layer_Name" at 577,-858.49 h60
M4 3D STEP Bottom:
  text ".Layer_Name" at 577,-858.49 h60
M5 Assembly Top:
  lines w10: -292,-930.17 6308,-930.17 ; -292,-726.83 6310,-726.83 ; -292,-523.5 -292,-1133.5 3713,-1133.5 6310,-1133.5 6310,-523.5 -291.5,-523.5 -291.5,-1133.5 1284,-1133.5 ; 2173,-1133.5 2173,-523.5 ; 3440,-726.83 3440,-523.5 ; 4280,-726.83 4280,-523.5 ; 4902,-1140 4902,-937.17
  text "COMPONENTS MARKED 'DNP' SHOULD NOT BE POPULATED." at 1153.5,-318.5 h60
  text "ASSEMBLY VARIANT:" at 1153,-434 h60
  text ".VariantName" at 2189,-434 h60
  text "PCB VIEWED FROM TOP SIDE" at -228.5,-655.67 h60
  text "BOARD #:" at 2248,-655.67 h60
  text ".PRJ_Number" at 2793.5,-655.67 h60
  text "REV:" at 3638,-655.67 h60
  text ".PCB_Rev" at 3929.5,-655.67 h60
  text "SVN REV:" at 4476,-655.67 h60
  text ".VersionControl_RevNumber" at 4982,-655.67 h60
  text "TID #:" at 2248,-859 h60
  text ".TID" at 2793.5,-859 h60
  text "PLOT NAME =" at -228.5,-1064.34 h60
  text ".plot_File_Name" at 577,-1064.34 h60
  text "GENERATED    :" at 2250,-1064.34 h60
  text ".Print_Date" at 3119.5,-1064.34 h60
  text ".Print_Time" at 3848.5,-1064.34 h60
  text "TEXAS INSTRUMENTS" at 5113,-1064.34 h60
M6 Assembly Bottom:
  lines w10: -292.5,-727.33 6309.5,-727.33 ; -290.5,-930.67 6309.5,-930.67 ; 1115.5,-1140.5 1115.5,-937.67 ; 1737.5,-727.33 1737.5,-524 ; 2577.5,-727.33 2577.5,-524 ; 3844.5,-1134 3844.5,-524 ; 4733.5,-1134 6309,-1134 6309,-524 -292.5,-524 -292.5,-1134 2304.5,-1134 6309.5,-1134 6309.5,-524
  text "COMPONENTS MARKED 'DNP' SHOULD NOT BE POPULATED." at 6102,-318 h60
  text ".VariantName" at 5058,-434 h60
  text "ASSEMBLY VARIANT:" at 6097,-434 h60
  text ".VersionControl_RevNumber" at 1035.5,-656.17 h60
  text "SVN REV:" at 1541.5,-656.17 h60
  text ".PCB_Rev" at 2088,-656.17 h60
  text "REV:" at 2379.5,-656.17 h60
  text ".PRJ_Number" at 3224,-656.17 h60
  text "BOARD #:" at 3769.5,-656.17 h60
  text "PCB VIEWED FROM BOTTOM SIDE" at 6246,-656.17 h60
  text ".TID" at 3224,-859.5 h60
  text "TID #:" at 3769.5,-859.5 h60
  text "TEXAS INSTRUMENTS" at 904.5,-1064.84 h60
  text ".Print_Time" at 2169,-1064.84 h60
  text ".Print_Date" at 2898,-1064.84 h60
  text "GENERATED    :" at 3767.5,-1064.84 h60
  text ".plot_File_Name" at 5440.5,-1064.84 h60
  text "PLOT NAME =" at 6246,-1064.84 h60
M9 Title Sheet:
  drawing of 57 lines, arcs and shapes, not listed
  text "1" at 739.84,8036.5 h70
  text "2" at 3235.5,8036.5 h70
  text "3" at 5724.84,8036.5 h70
  text "4" at 8231.51,8036.5 h70
  text "5" at 10730.5,8036.5 h70
  text "6" at 13235.5,8036.5 h70
  text "A" at -416.5,6893.5 h70
  text "A" at 14383.5,6893.5 h70
  text "B" at -416.5,4513.5 h70
  text "B" at 14383.5,4513.5 h70
  text "C" at -416.5,2138.5 h70
  text "C" at 14383.5,2138.5 h70
  text "PROJECT TITLE:" at 11343.5,277.5 h45
  text ".PRJ_Title" at 11393.5,144.17 h70
  text "DESIGNED FOR:" at 11343.5,-23.5 h45
  text ".PRJ_Customer" at 11393.5,-163.5 h70
  text "D" at -416.5,-231.5 h70
  text "D" at 14383.5,-231.5 h70
  text "FILE NAME:" at 11343.5,-323.5 h45
  text ".PCB_File_Name_No_Path" at 11393.5,-443.5 h70
  text "Texas Instruments (TI) and/or its licensors do not warrant the accuracy or completeness of this specification" at 6374,-605.34 h45
  text "ENGINEER:" at 11343.5,-613.5 h45
  text "LAYOUT BY:" at 12848.5,-613.5 h45
  text "or any information contained therein. TI and/or its licensors do not warrant that this design will meet" at 6329.01,-718 h45
  text ".PRJ_Engineer" at 11393.5,-768.49 h70
  text ".PCB_Layout" at 12899,-768.49 h70
  text "the specifications, will be suitable for your application or fit for any particular purpose, or will operate in" at 6329.01,-830.67 h45
  text ".Layer_Name" at 577,-858.49 h60
  text "ALTIUM DESIGNER VERSION:" at 12848.5,-923.5 h45
  text "an implementation. TI and/or its licensors do not warrant that the design is production worthy. You should" at 6329.01,-943.33 h45
  text "completely validate and test your design implementation to confirm the system functionality for your application." at 6374,-1056 h45
  text ".print_Scale" at 11393.5,-1056.83 h70
  text ".Application_BuildNumber" at 12899,-1056.83 h70
  text "1" at 739.84,-1263.5 h70
  text "2" at 3235.5,-1263.5 h70
  text "3" at 5724.84,-1263.5 h70
  text "4" at 8231.51,-1263.5 h70
  text "5" at 10730.5,-1263.5 h70
  text "6" at 13235.5,-1263.5 h70
M10 Fab Notes:
  drawing of 189 lines, arcs and shapes, not listed
  text "DESIGN INFORMATION" at 12382.02,6356.17 h60
  text "MIN. TRACK WIDTH:" at 11737.46,6224.05 h60
  text "8" at 12833.7,6224.05 h60
  text "MIL" at 12988.46,6224.05 h60
  text "7.874" at 12667.32,6102.36 h60
  text "MIN. CLEARANCE:" at 11737.46,6099.92 h60
  text "MIL" at 12988.46,6099.92 h60
  text "MIN. VIA PAD SIZE:" at 11737.46,5975.8 h60
  text "24" at 12803.71,5975.8 h60
  text "MIL" at 12988.46,5975.8 h60
  text "0.05mm (2MIL)" at 12432.46,5845.9 h60
  text "MINIMUM ANNULAR RING" at 11408.23,5837.67 h60
  text "EXTERNAL" at 13140.46,5837.67 h60
  text "PER" at 11608.23,5727.55 h60
  text "IPC-D-275 CLASS 2 LEVEL C" at 11828.23,5727.54 h60
  text "MIL, HOLES" at 13316.46,5627.07 h60
  text "+/-" at 12924,5618.48 h60
  text "+/-" at 13778,5618.48 h60
  text "REGISTRATION TOLERANCES:" at 11408.23,5617.42 h60
  text "METAL" at 12608,5617.42 h60
  text "5" at 13184.2,5617.42 h60
  text "3" at 14017.2,5617.42 h60
  text "MIL" at 14133.46,5617.42 h60
  text "HOLE SIZE TOLERANCE (UNLESS OTHERWISE SPECIFIED):" at 11408.23,5519.1 h60
  text "+/-" at 13778,5516.23 h60
  text "3" at 14017.2,5515.17 h60
  text "MIL" at 14133.46,5515.17 h60
  text "MATERIAL:" at 11333.46,5377.52 h60
  text "FR-4 High Tg" at 12319.9,5249 h60
  text "X" at 12175.46,5241.01 h60
  text "FR-4" at 11754.46,5236.49 h60
  text "OTHER" at 13242.46,5236.49 h60
  text "62 MIL (1.6mm) +/-10%" at 12074.56,5093.46 h60
  text "X" at 11954.46,5091.01 h60
  text "THICKNESS:" at 11408.23,5085.24 h60
  text "OTHER" at 13359.46,5085.24 h60
  text "TOLERANCE:" at 11408.23,4946.92 h60
  text "X" at 12256.46,4946.92 h60
  text "ANSI IPC-6012 TYPE 3 CLASS 2" at 12434.48,4946.92 h60
  text "OTHER +/-" at 12434.46,4802.73 h60
  text "BOW & TWIST:" at 11408.23,4657.54 h60
  text "X" at 12256.46,4657.54 h60
  text "ANSI IPC-6012 TYPE 3 CLASS 2" at 12434.48,4657.54 h60
  text "OTHER +/-" at 12434.46,4510.85 h60
  text "DRILLING:" at 11333.46,4380.23 h60
  text "NC_DRILL FILES" at 13094.46,4275.04 h60
  text "REFERENCE:" at 11408.23,4271.1 h60
  text "X" at 12065.46,4271.01 h60
  text "AS SHOWN" at 12243.46,4271.1 h60
  text "X" at 12966.46,4271.1 h60
  text "OTHER" at 13392.46,4128.85 h60
  text "PTH COPPER THICKNESS:" at 11407.91,4125.32 h60
  text "X" at 12547.14,4125.32 h60
  text "20-30 um" at 12675.14,4125.32 h60
  text "BOARD FINISH:" at 11333.46,3977.73 h60
  text "SILKSCREEN:" at 11488.68,3867.6 h60
  text "X" at 12446.46,3867.6 h60
  text "TOP" at 12563.46,3867.6 h60
  text "X" at 12956.46,3867.6 h60
  text "BOTTOM" at 13074.46,3867.6 h60
  text "SILKSCREEN COLOR:" at 11488.68,3712.41 h60
  text "X" at 12445.46,3712.41 h60
  text "WHITE" at 12563.46,3712.41 h60
  text "OTHER" at 13074.46,3712.41 h60
  text "X" at 12576.46,3568.96 h60
  text "GREEN" at 12694.46,3568.96 h60
  text "OTHER" at 13312.46,3568.96 h60
  text "SOLDER RESIST COLOR:" at 11488.68,3562.1 h60
  text "X" at 12576.46,3414.71 h60
  text "MATTE" at 12694.46,3414.71 h60
  text "SEMI-GLOSS" at 13312,3414.07 h60
  text "IMMERSION GOLD (ENIG)" at 12394.46,3241.94 h60
  text "ENEPIG" at 13732,3234.72 h60
  text "SURFACE FINISH:" at 11333.46,3233.72 h60
  text "X" at 12216.46,3233.72 h60
  text "IMM. TIN/SILVER OR EQUIV" at 11663,3096.4 h60
  text "OTHER" at 13094.46,3092.47 h60
  text "ARRAY/PANEL:" at 11333.46,2937.09 h60
  text "CUT AND TRIM PER M1 BOARD OUTLINE" at 12394.46,2928.87 h60
  text "N.C. ROUTE" at 12394.46,2792.9 h60
  text "X" at 13082.46,2792.9 h60
  text "V. SCORE" at 13260.46,2792.9 h60
  text "CERTIFICATION:" at 11333.46,2663.77 h60
  text "MATERIALS AND WORKMANSHIP FOR ALL PCBS" at 12058.46,2663.77 h60
  text "TO MEET OR EXCEED THE REQUIREMENTS OF:" at 12058.46,2569.71 h60
  text "X" at 11695.97,2441.08 h60
  text "ANSI IPC-A-600F CLASS ->" at 11823.96,2441.08 h60
  text "X" at 13471.97,2441.08 h60
  text "2" at 13581.96,2441.08 h60
  text "1" at 13266.96,2439.58 h60
  text "3" at 13935.96,2439.58 h60
  text "X" at 12507.97,2293.39 h60
  text "RoHS" at 12635.96,2293.39 h60
  text "OTHER" at 13280.36,2293.39 h60
  text "PER ORDER" at 13677.42,2293.39 h60
  text "ALL BOARDS MUST MEET OR EXCEED UL94-V0 REQUIREMENTS." at 11361,2139.57 h60
  text "PCB MUST BEAR THE UL94V-0 UL REGISTERED MATERIAL ID NUMBER" at 11361,2023.5 h60
  text "ADDITIONAL REQUIREMENTS:" at 11333.46,1854.08 h60
  text "MICROSECTION:" at 11408.23,1746.95 h60
  text "YES" at 12313.96,1746.95 h60
  text "REQUIRED" at 13175.46,1602.62 h60
  text "BARE BOARD ELEC. TEST:" at 11408.23,1599.76 h60
  text "NONE" at 12713.96,1599.76 h60
  text "X" at 13057.46,1599.76 h60
  text "PER ORDER" at 13767.46,1599.76 h60
  text "XX MIL VIAS REQUIRE NON-CONDUCTIVE FILL AND PLANARIZE" at 11576.38,1394.82 h59
  text "XX MIL VIAS REQUIRE CONDUCTIVE FILL AND PLANARIZE" at 11584.38,1290.84 h60
  text "OUTER XX MIL TRACES REQUIRE 50 OHM SINGLE-ENDED IMPEDANCE" at 11583.39,1127.46 h58
  text "LAYER 2 & 3 (INNER LAYERS) XX MIL WIDE, XX MIL SPACE / TRACES REQUIRE 100 OHM DIFFERENTIAL IMPEDANCE" at 11575.39,891.74 h60
  text ".Layer_Name" at 577,-858.49 h60
M11 Gerber Information:
  lines w10: -292,-930.17 6308,-930.17 ; -292,-726.83 6310,-726.83 ; -292,-523.5 -292,-1133.5 3713,-1133.5 6310,-1133.5 6310,-523.5 -291.5,-523.5 -291.5,-1133.5 1284,-1133.5 ; 2173,-1133.5 2173,-523.5 ; 3440,-726.83 3440,-523.5 ; 4280,-726.83 4280,-523.5 ; 4902,-1140 4902,-937.17
  text "ALL ARTWORK VIEWED FROM TOP SIDE" at -228.5,-655.67 h60
  text "BOARD #:" at 2248,-655.67 h60
  text ".PRJ_Number" at 2793.5,-655.67 h60
  text "REV:" at 3638,-655.67 h60
  text ".PCB_Rev" at 3929.5,-655.67 h60
  text "SVN REV:" at 4476,-655.67 h60
  text ".VersionControl_RevNumber" at 4982,-655.67 h60
  text "LAYER NAME =" at -228.5,-858.49 h60
  text "TID #:" at 2248,-859 h60
  text ".TID" at 2793.5,-859 h60
  text "PLOT NAME =" at -228.5,-1064.34 h60
  text ".plot_File_Name" at 577,-1064.34 h60
  text "GENERATED    :" at 2250,-1064.34 h60
  text ".Print_Date" at 3119.5,-1064.34 h60
  text ".Print_Time" at 3848.5,-1064.34 h60
  text "TEXAS INSTRUMENTS" at 5113,-1064.34 h60
M12 Stackup:
  drawing of 295 lines, arcs and shapes, not listed
  text "Layer" at 6100.04,7276.55 h60
  text "Name" at 6509.95,7276.55 h60
  text "Material" at 7439.7,7276.55 h60
  text "Thickness" at 8299.47,7276.55 h60
  text "Constant" at 8949.3,7276.55 h60
  text "Board Layer Stack" at 9519.16,7276.55 h60
  text "Top Overlay" at 6509.95,7156.55 h60
  text "Top Solder" at 6509.95,7036.55 h60
  text "Solder Resist" at 7439.7,7036.55 h60
  text "0.40mil" at 8299.47,7036.55 h60
  text "3.5" at 8949.3,7036.55 h60
  text "1" at 6100.04,6916.55 h60
  text "Top Layer" at 6509.95,6916.55 h60
  text "1.40mil" at 8299.47,6916.55 h60
  text "Dielectric 1" at 6509.95,6796.55 h60
  text "PP-006" at 7439.7,6796.55 h60
  text "2.80mil" at 8299.47,6796.55 h60
  text "4.1" at 8949.3,6796.55 h60
  text "2" at 6100.04,6676.55 h60
  text "Layer 1" at 6509.95,6676.55 h60
  text "CF-004" at 7439.7,6676.55 h60
  text "1.38mil" at 8299.47,6676.55 h60
  text "Dielectric1" at 6509.95,6556.55 h60
  text "FR-4 High Tg" at 7439.7,6556.55 h60
  text "59.20mil" at 8299.47,6556.55 h60
  text "4.8" at 8949.3,6556.55 h60
  text "3" at 6100.04,6436.55 h60
  text "Layer 2" at 6509.95,6436.55 h60
  text "CF-004" at 7439.7,6436.55 h60
  text "1.38mil" at 8299.47,6436.55 h60
  text "Dielectric 2" at 6509.95,6316.55 h60
  text "PP-006" at 7439.7,6316.55 h60
  text "2.80mil" at 8299.47,6316.55 h60
  text "4.1" at 8949.3,6316.55 h60
  text "4" at 6100.04,6196.55 h60
  text "Bottom Layer" at 6509.95,6196.55 h60
  text "1.40mil" at 8299.47,6196.55 h60
  text "Bottom Solder" at 6509.95,6076.55 h60
  text "Solder Resist" at 7439.7,6076.55 h60
  text "0.40mil" at 8299.47,6076.55 h60
  text "3.5" at 8949.3,6076.55 h60
  text "Bottom Overlay" at 6509.95,5956.55 h60
  text ".Layer_Name" at 577,-858.49 h60
M13 Component Bodies Top:
  text ".Layer_Name" at 577,-858.49 h60
M14 Component Bodies Bottom:
  text ".Layer_Name" at 577,-858.49 h60
M15 Courtyards Top:
  text ".Layer_Name" at 577,-858.49 h60
M16 Courtyards Bottom:
  text ".Layer_Name" at 577,-858.49 h60
Drill Drawing:
  circle w10: c5363.72,2544.36 r27.63
  lines w10: 5336.09,2199.03 5391.34,2199.03 5363.72,2143.78 5336.09,2199.03 ; 5336.09,2268.1 5391.34,2268.1 5391.34,2323.35 5336.09,2323.35 5336.09,2268.1 ; 5336.09,2406.23 5349.9,2406.23 5363.72,2392.42 5377.53,2406.23 5391.34,2406.23 5377.53,2420.04 5391.34,2433.86 5377.53,2433.86 5363.72,2447.67 5349.9,2433.86 5336.09,2433.86 5349.9,2420.04 5336.09,2406.23 ; 5336.09,2654.87 5349.9,2654.87 5349.9,2641.06 5377.53,2641.06 5377.53,2654.87 5391.34,2654.87 5391.34,2682.5 5377.53,2682.5 5377.53,2696.31 5349.9,2696.31 5349.9,2682.5 5336.09,2682.5 5336.09,2654.87 ; 5336.09,2765.38 5336.09,2779.19 5349.9,2793 5336.09,2806.82 5336.09,2820.63 5349.9,2820.63 5363.72,2806.82 5377.53,2820.63 5391.34,2820.63 5391.34,2806.82 5377.53,2793 5391.34,2779.19 5391.34,2765.38 5377.53,2765.38 5363.72,2779.19 5349.9,2765.38 5336.09,2765.38 ; 5336.09,2889.7 5363.72,2903.51 5391.34,2889.7 5377.53,2917.32 5391.34,2944.95 5363.72,2931.14 5336.09,2944.95 5349.9,2917.32 5336.09,2889.7 ; 5336.09,3014.02 5391.34,3014.02 5391.34,3069.27 5336.09,3069.27 5336.09,3014.02 ; 5336.09,3193.59 5391.34,3193.59 5363.72,3138.34 5336.09,3193.59 ; 5336.09,3290.28 5363.72,3262.66 5391.34,3290.28 5363.72,3317.91 5336.09,3290.28 ; 5347.14,3025.07 5380.29,3025.07 5380.29,3058.22 5347.14,3058.22 5347.14,3025.07 ; 5347.14,3182.54 5380.29,3182.54 5363.72,3149.39 5347.14,3182.54
  lines w12: 5286,2106.48 8517.49,2106.48 ; 5286,3349.68 8517.49,3349.68 ; 5623.86,1982.16 5623.86,3474 ; 5955.86,1982.16 5955.86,3474 ; 6592.43,1982.16 6592.43,3474 ; 6851.57,1982.16 6851.57,3474 ; 7226.72,1982.16 7226.72,3474 ; 7951.05,1982.16 7951.05,3474 ; 5286,1982.16 8517.49,1982.16 8517.49,3474 5286,3474 5286,1982.16
  text "Symbol" at 5360.59,3386.98 h72
  text "Quantity" at 5661.16,3386.98 h72
  text "Finished Hole Size" at 5993.16,3386.98 h72
  text "Plated" at 6629.72,3386.98 h72
  text "Hole Type" at 6888.86,3386.98 h72
  text "Drill Layer Pair" at 7264.02,3386.98 h72
  text "Hole Tolerance" at 7988.35,3386.98 h72
  text "46" at 5661.16,3262.66 h60
  text "7.87mil (0.200mm)" at 5993.16,3262.66 h60
  text "PTH" at 6629.72,3262.66 h60
  text "Round" at 6888.86,3262.66 h60
  text "Top Layer - Bottom Layer" at 7264.02,3262.66 h60
  text "4" at 5661.16,3138.34 h60
  text "8.00mil (0.203mm)" at 5993.16,3138.34 h60
  text "PTH" at 6629.72,3138.34 h60
  text "Round" at 6888.86,3138.34 h60
  text "Top Layer - Bottom Layer" at 7264.02,3138.34 h60
  text "593" at 5661.16,3014.02 h60
  text "10.00mil (0.254mm)" at 5993.16,3014.02 h60
  text "PTH" at 6629.72,3014.02 h60
  text "Round" at 6888.86,3014.02 h60
  text "Top Layer - Bottom Layer" at 7264.02,3014.02 h60
  text "40" at 5661.16,2889.7 h60
  text "40.00mil (1.016mm)" at 5993.16,2889.7 h60
  text "PTH" at 6629.72,2889.7 h60
  text "Round" at 6888.86,2889.7 h60
  text "Top Layer - Bottom Layer" at 7264.02,2889.7 h60
  text "4" at 5661.16,2765.38 h60
  text "45.28mil (1.150mm)" at 5993.16,2765.38 h60
  text "PTH" at 6629.72,2765.38 h60
  text "Round" at 6888.86,2765.38 h60
  text "Top Layer - Bottom Layer" at 7264.02,2765.38 h60
  text "2" at 5661.16,2641.06 h60
  text "59.06mil (1.500mm)" at 5993.16,2641.06 h60
  text "PTH" at 6629.72,2641.06 h60
  text "Round" at 6888.86,2641.06 h60
  text "Top Layer - Bottom Layer" at 7264.02,2641.06 h60
  text "4" at 5661.16,2516.74 h60
  text "125.98mil (3.200mm)" at 5993.16,2516.74 h60
  text "PTH" at 6629.72,2516.74 h60
  text "Round" at 6888.86,2516.74 h60
  text "Top Layer - Bottom Layer" at 7264.02,2516.74 h60
  text "4" at 5661.16,2392.42 h60
  text "27.56mil (0.700mm)" at 5993.16,2392.42 h60
  text "PTH" at 6629.72,2392.42 h60
  text "Slot" at 6888.86,2392.42 h60
  text "Top Layer - Bottom Layer" at 7264.02,2392.42 h60
  text "4" at 5661.16,2268.1 h60
  text "51.18mil (1.300mm)" at 5993.16,2268.1 h60
  text "PTH" at 6629.72,2268.1 h60
  text "Slot" at 6888.86,2268.1 h60
  text "Top Layer - Bottom Layer" at 7264.02,2268.1 h60
  text "4" at 5661.16,2143.78 h60
  text "59.06mil (1.500mm)" at 5993.16,2143.78 h60
  text "PTH" at 6629.72,2143.78 h60
  text "Slot" at 6888.86,2143.78 h60
  text "Top Layer - Bottom Layer" at 7264.02,2143.78 h60
  text "705 Total" at 5661.16,2019.46 h60
  text "Slot definitions :" at 5360.59,1932.43 h60
  text "Routed Path Length" at 5811.31,1932.43 h60
  text "= Calculated from tool start centre position to tool end centre position." at 6351.05,1932.43 h60
  text "Hole Length" at 5811.31,1882.7 h60
  text "= Routed Path Length + Tool Size = Slot length as defined in the PCB layout" at 6151.24,1882.7 h60
  text ".Layer_Name" at 577,-858.49 h60
M17 Embedded Cavity:
  text ".Layer_Name" at 577,-858.49 h60
M18 Embedded Assembly:
  text ".Layer_Name" at 577,-858.49 h60
M19 Embedded Keepout:
  text ".Layer_Name" at 577,-858.49 h60

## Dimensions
0,-400 to 1000,-400 on M2 Board Dimensions
0,0 to 4950,0 on M2 Board Dimensions
0,0 to 0,3450 on M2 Board Dimensions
